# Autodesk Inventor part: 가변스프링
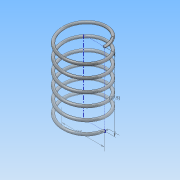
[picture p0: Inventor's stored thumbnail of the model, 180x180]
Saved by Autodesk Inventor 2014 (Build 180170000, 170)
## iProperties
Created: 2016-12
Part Number: 가변스프링
Material: 스테인레스 스틸
Document SubType Name: Modeling
Designer: NET
Density: 8.08 g/cm^3
Appearance: 반연마
Mass: 1.89763 g
Surface Area: 9.47796 cm^2
Volume: 0.234856 cm^3
Author: NET
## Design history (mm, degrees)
sketch "스케치1"
  geometry: L1 (0, 0)-(-8, 0); L2 (-8, 0)-(-8, 27.5); L3 (-8, 27.5)-(0, 27.5); L4 (0, 27.5)-(0, 0); C1 r 0.5 at (-8, 0)
  constraints: 8 end point, 2 parallel, 1 centre point, 1 coincident, 1 horizontal, 1 perpendicular
  dimensions: "d1" = 16 diameter of L2 L4; "d2" = 27.5 distance between parallel lines of L1 L3 (derived); "d3" = 1 diameter of C1
feature "코일1" sketch "스케치1" pitch "d4" = 10; turns "d6" = 6; dims "d5" = 27.5 (= d2), "d7" = 0, angle "d8" = 90 deg, angle "d9" = 90 deg, "d10" = 0, "d11" = 0
sketch "스케치2"
  geometry: L1 (7.5, 0)-(8.5, 0) reference; 1 further point
  constraints: 1 horizontal alignment
extrude "돌출1" cut sketch "스케치2" distance "d12" = 10; taper "d13" = 0 deg
node "작업 평면1"
sketch "스케치3"
  geometry: L1 (-7.5, 0)-(-8.5, 0) reference; 1 further point
  constraints: 1 horizontal alignment
extrude "돌출2" cut sketch "스케치3" distance "d14" = 10; taper "d15" = 0 deg
node "솔리드1"
node "절단 모서리 투영1"
node "절단 모서리 투영2"
